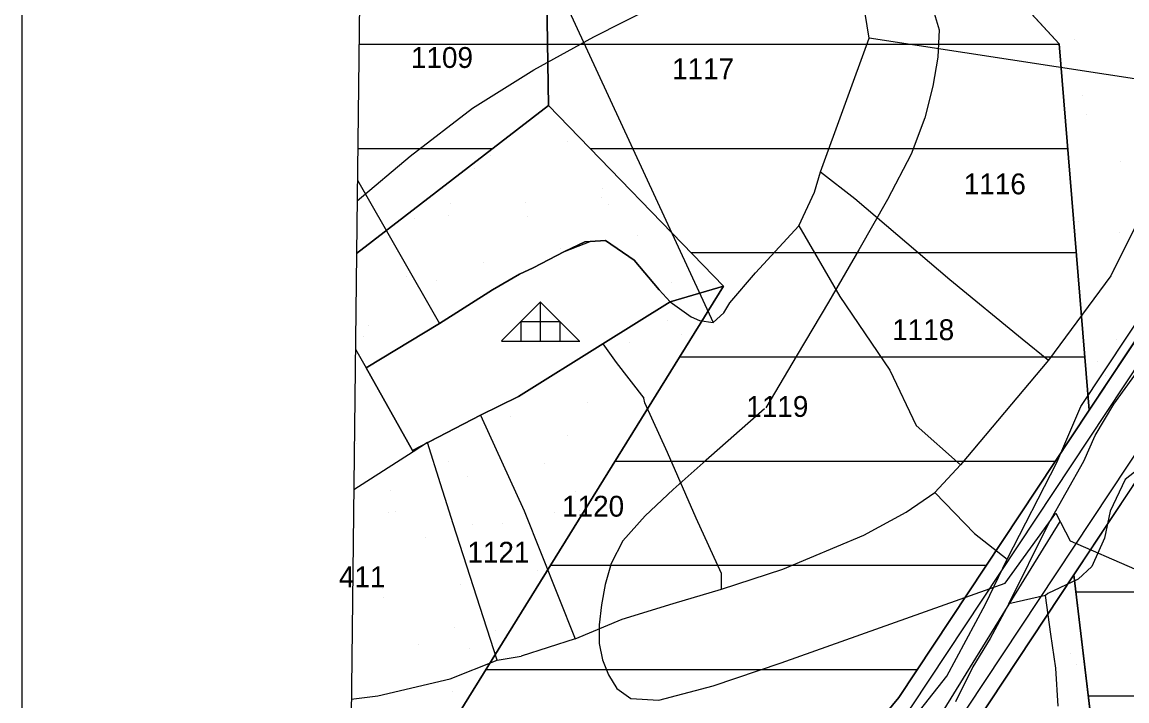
# Model space of a CAD drawing. Extents: x 410727 to 412947, y 4463506 to 4466382.
# Drawn here: x 410732.3 to 410944.2, y 4466165.1 to 4466295.3 of the extents above; entities that cross this region are included whole.
import ezdxf

# ---------------------------------------------------------------- set-up
doc = ezdxf.new("R2010")
doc.units = 0
for name, color, linetype in [('ADAKENARI', 7, 'Continuous'), ('KALDIRIM', 7, 'Continuous'), ('KDS_PARSEL_NO', 7, 'Continuous'), ('KDS_PL', 7, 'Continuous'), ('LJ_ÇERÇEVE', 7, 'Continuous'), ('PL_AYA_ORMAN', 7, 'Continuous'), ('PL_AYA_PARK_DINLENME', 7, 'Continuous'), ('PL_KON_ONE_50', 7, 'Continuous'), ('TR_GELİŞME_KONUT_ÇOKAZ', 7, 'Continuous'), ('TR_ORMAN', 7, 'Continuous'), ('TR_PARKALANI', 7, 'Continuous'), ('Yerlesime_uygunluk_sınırı', 7, 'Continuous')]:
    doc.layers.add(name, color=color, linetype=linetype)

msp = doc.modelspace()

# ---------------------------------------------------------------- linework, layer by layer
at = {"layer": 'ADAKENARI'}
for p, q in [((410931.26, 4466291.1), (410905.8, 4466318.77)), ((410984.87, 4466293.13), (410937.01, 4466220.86)), ((410937.01, 4466220.86), (410931.26, 4466291.1)), ((410934.05, 4466189.23), (410970.35, 4466244.04)), ((410937.01, 4466220.86), (410900.49, 4466165.73)), ((410938.28, 4466153.9), (410934.05, 4466189.23))]:
    msp.add_line(p, q, dxfattribs=at)
for points in [[(410795.11, 4466136.69), (410805.11, 4466144.92), (410866.88, 4466244.62), (410833.32, 4466279.27), (410832.84, 4466307.82), (410865.03, 4466330.16), (410877.28, 4466326.74), (410905.8, 4466318.77), (410931.26, 4466291.1), (410937.01, 4466220.86), (410900.49, 4466165.73), (410879.24, 4466140.03), (410850.95, 4466105.81), (410843.66, 4466098.87), (410832.15, 4466087.93), (410816.2, 4466116.02), (410794.68, 4466100.2)], [(410816.68, 4466331), (410832.84, 4466307.82), (410833.32, 4466279.27), (410796.46, 4466250.92)], [(410796.46, 4466250.92), (410833.32, 4466279.27), (410866.88, 4466244.62), (410856.65, 4466241.61), (410854.49, 4466243.9), (410849.71, 4466249.6), (410844.2, 4466253.37), (410840.27, 4466253.16), (410836.39, 4466251.28), (410830.37, 4466248.16), (410827.75, 4466246.92), (410822.57, 4466243.9), (410812.36, 4466237.47), (410798.29, 4466228.95), (410807.2, 4466213.12), (410820.24, 4466219.87), (410827.53, 4466223.46), (410843.7, 4466233.54), (410856.65, 4466241.61), (410866.88, 4466244.62), (410805.11, 4466144.92)], [(410940.58, 4466134.71), (410895.48, 4466136.13), (410912.56, 4466156.78), (410934.05, 4466189.23), (410938.28, 4466153.9), (410940.58, 4466134.71)]]:
    msp.add_lwpolyline(points, dxfattribs=at)
at = {"layer": 'KALDIRIM'}
msp.add_lwpolyline([(410877.26, 4466132.92), (410902.91, 4466163.94), (410984.73, 4466287.49), (410992.24, 4466282.52), (410910.15, 4466158.57), (410883.93, 4466126.86)], dxfattribs=at)
at = {"layer": 'KDS_PL'}
for p, q in [((410834.19, 4466304.11), (410864.85, 4466237.66)), ((410894.78, 4466292.22), (410893.62, 4466299.29)), ((410885.49, 4466266.55), (410894.78, 4466292.22)), ((410958.96, 4466282.37), (410894.78, 4466292.22)), ((410884.31, 4466262.69), (410885.49, 4466266.55)), ((410885.49, 4466266.55), (410892.04, 4466261.44)), ((410796.63, 4466264.96), (410812.36, 4466237.47)), ((410881.3, 4466256.2), (410884.31, 4466262.69)), ((410892.04, 4466261.44), (410910.29, 4466245.88)), ((410947.29, 4466258.94), (410941.14, 4466246.62)), ((410872.97, 4466247.16), (410881.3, 4466256.2)), ((410881.3, 4466256.2), (410889.16, 4466242.64)), ((410836.39, 4466251.28), (410841.26, 4466253.22)), ((410841.26, 4466253.22), (410844.2, 4466253.37)), ((410844.2, 4466253.37), (410849.71, 4466249.6)), ((410830.37, 4466248.16), (410836.39, 4466251.28)), ((410935.37, 4466221.54), (410954.9, 4466251.01)), ((410849.71, 4466249.6), (410854.49, 4466243.9)), ((410822.57, 4466243.9), (410827.75, 4466246.92)), ((410827.75, 4466246.92), (410830.37, 4466248.16)), ((410868.06, 4466241.46), (410872.97, 4466247.16)), ((410941.14, 4466246.62), (410929.18, 4466230.45)), ((410910.29, 4466245.88), (410924.12, 4466234.54)), ((410812.36, 4466237.47), (410822.57, 4466243.9)), ((410854.49, 4466243.9), (410856.65, 4466241.61)), ((410889.16, 4466242.64), (410898.78, 4466228.51)), ((410843.7, 4466233.54), (410856.65, 4466241.61)), ((410856.65, 4466241.61), (410860.66, 4466238.72)), ((410866.95, 4466239.49), (410868.06, 4466241.46)), ((410860.66, 4466238.72), (410862.23, 4466238.06)), ((410862.23, 4466238.06), (410864.85, 4466237.66)), ((410864.85, 4466237.66), (410866.95, 4466239.49)), ((410798.29, 4466228.95), (410812.36, 4466237.47)), ((410924.12, 4466234.54), (410929.18, 4466230.45)), ((410827.53, 4466223.46), (410843.7, 4466233.54)), ((410843.7, 4466233.54), (410846.3, 4466230)), ((410846.3, 4466230), (410851.58, 4466223.15)), ((410929.18, 4466230.45), (410912.3, 4466210.35)), ((410941.71, 4466221.99), (410948.25, 4466231)), ((410798.29, 4466228.95), (410807.35, 4466212.86)), ((410898.78, 4466228.51), (410903.83, 4466217.9)), ((410820.24, 4466219.87), (410827.53, 4466223.46)), ((410851.79, 4466222.26), (410851.58, 4466223.15)), ((410856.15, 4466212.71), (410851.79, 4466222.26)), ((410930.81, 4466210.8), (410935.37, 4466221.54)), ((410938.16, 4466215.99), (410941.71, 4466221.99)), ((410810.09, 4466214.62), (410820.24, 4466219.87)), ((410820.24, 4466219.87), (410828.62, 4466201.51)), ((410912.3, 4466210.35), (410903.83, 4466217.9)), ((410810.09, 4466214.62), (410807.35, 4466212.86)), ((410812.58, 4466206.72), (410810.09, 4466214.62)), ((410935.98, 4466211.07), (410938.16, 4466215.99)), ((410807.35, 4466212.86), (410795.93, 4466205.55)), ((410861.6, 4466200.15), (410856.15, 4466212.71)), ((410907.37, 4466205.07), (410912.3, 4466210.35)), ((410921.27, 4466192.23), (410930.81, 4466210.8)), ((410929.17, 4466199.06), (410935.98, 4466211.07)), ((410949.7, 4466212.12), (410943.9, 4466207.55)), ((410813.85, 4466202.7), (410812.58, 4466206.72)), ((410943.9, 4466207.55), (410941.06, 4466201.49)), ((410901.92, 4466201.24), (410907.37, 4466205.07)), ((410907.37, 4466205.07), (410915, 4466197.15)), ((410815, 4466199.06), (410813.85, 4466202.7)), ((410828.62, 4466201.51), (410838.43, 4466176.94)), ((410866.5, 4466189.5), (410861.6, 4466200.15)), ((410893.75, 4466196.87), (410901.92, 4466201.24)), ((410941.06, 4466201.49), (410939.95, 4466196.3)), ((410823.44, 4466172.85), (410815, 4466199.06)), ((410921.57, 4466183.69), (410929.17, 4466199.06)), ((410878.22, 4466190.32), (410893.75, 4466196.87)), ((410915, 4466197.15), (410921.27, 4466192.23)), ((410939.95, 4466196.3), (410937.48, 4466190.86)), ((410917.14, 4466183.62), (410921.27, 4466192.23)), ((410866.5, 4466186.5), (410878.22, 4466190.32)), ((410866.5, 4466186.5), (410866.5, 4466189.5)), ((410937.48, 4466190.86), (410934.89, 4466188.39)), ((410934.89, 4466188.39), (410929.09, 4466185.67)), ((410857.23, 4466183.77), (410866.5, 4466186.5)), ((410928.6, 4466185.3), (410921.57, 4466183.69)), ((410929.09, 4466185.67), (410928.6, 4466185.3)), ((410929.64, 4466177.86), (410928.6, 4466185.3)), ((410847.42, 4466180.76), (410857.23, 4466183.77)), ((410909.67, 4466169.8), (410917.14, 4466183.62)), ((410921.57, 4466183.69), (410917.99, 4466177.01)), ((410838.43, 4466176.94), (410847.42, 4466180.76)), ((410838.43, 4466176.94), (410828.08, 4466173.67)), ((410917.99, 4466177.01), (410914.66, 4466171.57)), ((410930.61, 4466171.31), (410929.64, 4466177.86)), ((410814.45, 4466169.3), (410823.44, 4466172.85)), ((410823.44, 4466172.85), (410828.08, 4466173.67)), ((410914.66, 4466171.57), (410911.33, 4466164.9)), ((410931.03, 4466164.06), (410930.61, 4466171.31)), ((410800.55, 4466166.02), (410814.45, 4466169.3)), ((410902.77, 4466161.05), (410909.67, 4466169.8)), ((410795.45, 4466165.4), (410800.55, 4466166.02))]:
    msp.add_line(p, q, dxfattribs=at)
msp.add_lwpolyline([(410796.25, 4466232.55), (410798.29, 4466228.95)], dxfattribs=at)
at = {"layer": 'LJ_ÇERÇEVE'}
msp.add_lwpolyline([(410732.32, 4466381.6), (412946.74, 4466381.6), (412946.74, 4463506.16), (410732.32, 4463506.16)], close=True, dxfattribs=at)
at = {"layer": 'PL_AYA_ORMAN'}
msp.add_lwpolyline([(410856.65, 4466241.61), (410854.49, 4466243.9), (410849.71, 4466249.6), (410844.2, 4466253.37), (410840.27, 4466253.16), (410836.39, 4466251.28), (410830.37, 4466248.16), (410827.75, 4466246.92), (410822.57, 4466243.9), (410812.36, 4466237.47), (410798.29, 4466228.95), (410807.2, 4466213.12), (410820.24, 4466219.87), (410827.53, 4466223.46), (410843.7, 4466233.54), (410856.65, 4466241.61)], dxfattribs=at)
at = {"layer": 'PL_AYA_PARK_DINLENME'}
for points in [[(410966.77, 4466329.24), (410952.62, 4466329.41), (410948.75, 4466326.83), (410945.69, 4466329.49), (410864.92, 4466330.44), (410865.03, 4466330.16), (410905.8, 4466318.77), (410931.26, 4466291.1), (410937.01, 4466220.86), (410984.87, 4466293.13), (410984.62, 4466304.63), (410966.77, 4466329.24)], [(410796.46, 4466250.92), (410795.35, 4466156.58), (410805.11, 4466144.92), (410866.88, 4466244.62), (410833.32, 4466279.27), (410796.46, 4466250.92)], [(410843.7, 4466233.54), (410827.53, 4466223.46), (410820.24, 4466219.87), (410807.2, 4466213.12), (410798.29, 4466228.95), (410812.36, 4466237.47), (410822.57, 4466243.9), (410827.75, 4466246.92), (410830.37, 4466248.16), (410836.39, 4466251.28), (410840.27, 4466253.16), (410844.2, 4466253.37), (410849.71, 4466249.6), (410854.49, 4466243.9), (410856.65, 4466241.61), (410843.7, 4466233.54)], [(410938.28, 4466153.9), (410934.05, 4466189.23), (410912.56, 4466156.78), (410895.48, 4466136.13), (410940.58, 4466134.71), (410938.28, 4466153.9)]]:
    msp.add_lwpolyline(points, dxfattribs=at)
at = {"layer": 'PL_KON_ONE_50'}
for points in [[(410816.68, 4466331), (410797.42, 4466331.23), (410796.46, 4466250.92), (410833.32, 4466279.27), (410866.88, 4466244.62), (410805.11, 4466144.92), (410795.11, 4466136.69), (410794.68, 4466100.2), (410816.2, 4466116.02), (410832.15, 4466087.93), (410843.66, 4466098.87), (410850.95, 4466105.81), (410879.24, 4466140.03), (410900.49, 4466165.73), (410937.01, 4466220.86), (410931.26, 4466291.1), (410905.8, 4466318.77), (410877.28, 4466326.74), (410865.03, 4466330.16), (410861.62, 4466327.79), (410841.62, 4466313.92), (410832.84, 4466307.82), (410821.62, 4466323.91), (410816.68, 4466331)], [(411018.73, 4466159.08), (411019.64, 4466094.39), (411040.6, 4466094.16), (411083.21, 4466088.38), (411127.43, 4466096.15), (411139.34, 4466102.02), (411143.99, 4466106.28), (411135.74, 4466178.25), (411069.2, 4466174.92), (411071.88, 4466196.56), (411061.36, 4466220.11), (411049.97, 4466245.63), (410970.35, 4466244.04), (410934.05, 4466189.23), (410938.28, 4466153.9), (410984.99, 4466158.37), (411018.73, 4466159.08)]]:
    msp.add_lwpolyline(points, dxfattribs=at)
at = {"layer": 'TR_GELİŞME_KONUT_ÇOKAZ'}
for p, q in [((410796.94, 4466291.07), (410833.12, 4466291.07)), ((410833.12, 4466291.07), (410833.12, 4466291.07)), ((410833.12, 4466291.07), (410931.26, 4466291.07)), ((410796.7, 4466271.07), (410822.65, 4466271.07)), ((410841.27, 4466271.07), (410932.9, 4466271.07)), ((410796.47, 4466251.07), (410796.66, 4466251.07)), ((410860.64, 4466251.07), (410934.54, 4466251.07)), ((410858.48, 4466231.07), (410936.17, 4466231.07)), ((410846.09, 4466211.07), (410930.52, 4466211.07)), ((410833.7, 4466191.07), (410917.28, 4466191.07)), ((410934.44, 4466186), (411014.83, 4466186)), ((410821.31, 4466171.07), (410904.03, 4466171.07)), ((410936.83, 4466166), (411137.14, 4466166))]:
    msp.add_line(p, q, dxfattribs=at)
at = {"layer": 'TR_ORMAN'}
for p, q in [((410824.29, 4466234.11), (410831.78, 4466241.61)), ((410839.19, 4466234.15), (410831.69, 4466241.65)), ((410831.79, 4466234.1), (410831.79, 4466241.6)), ((410828.04, 4466234.1), (410828.04, 4466237.85)), ((410828.04, 4466237.85), (410835.54, 4466237.85)), ((410835.54, 4466234.1), (410835.54, 4466237.85)), ((410824.29, 4466234.1), (410839.29, 4466234.1))]:
    msp.add_line(p, q, dxfattribs=at)
at = {"layer": 'TR_PARKALANI'}
for p, q in [((410934.19, 4466291.93), (410934.19, 4466291.93)), ((410934.19, 4466291.93), (410934.19, 4466291.93)), ((410934.19, 4466291.93), (410934.19, 4466291.93)), ((410935.67, 4466281.18), (410935.67, 4466281.18)), ((410935.67, 4466281.18), (410935.67, 4466281.18)), ((410935.67, 4466281.18), (410935.67, 4466281.18)), ((410935.67, 4466281.18), (410935.67, 4466281.18)), ((410935.67, 4466281.18), (410935.67, 4466281.18)), ((410935.67, 4466281.18), (410935.67, 4466281.18)), ((410936.44, 4466277.62), (410936.44, 4466277.62)), ((410936.44, 4466277.62), (410936.44, 4466277.62)), ((410936.44, 4466277.62), (410936.44, 4466277.62)), ((410936.44, 4466277.62), (410936.44, 4466277.62)), ((410936.44, 4466277.62), (410936.44, 4466277.62)), ((410936.44, 4466277.62), (410936.44, 4466277.62)), ((410836.97, 4466272.35), (410836.97, 4466272.35)), ((410836.97, 4466272.35), (410836.97, 4466272.35)), ((410822.2, 4466269.74), (410822.2, 4466269.74)), ((410822.2, 4466269.74), (410822.2, 4466269.74)), ((410943.1, 4466268.64), (410943.1, 4466268.64)), ((410943.1, 4466268.64), (410943.1, 4466268.64)), ((410943.1, 4466268.64), (410943.1, 4466268.64)), ((410943.1, 4466268.64), (410943.1, 4466268.64)), ((410943.1, 4466268.64), (410943.1, 4466268.64)), ((410943.1, 4466268.64), (410943.1, 4466268.64)), ((410819.09, 4466267.26), (410819.09, 4466267.26)), ((410843.63, 4466263.37), (410843.63, 4466263.37)), ((410843.63, 4466263.37), (410843.63, 4466263.37)), ((410843.44, 4466261.58), (410843.44, 4466261.58)), ((410843.44, 4466261.58), (410843.44, 4466261.58)), ((410814.42, 4466260.58), (410814.42, 4466260.58)), ((410828.86, 4466260.76), (410828.86, 4466260.76)), ((410828.86, 4466260.76), (410828.86, 4466260.76)), ((410844.84, 4466260.3), (410844.84, 4466260.3)), ((410807.6, 4466257.62), (410807.6, 4466257.62)), ((410807.6, 4466257.62), (410807.6, 4466257.62)), ((410814.09, 4466258.16), (410814.09, 4466258.16)), ((410814.09, 4466258.16), (410814.09, 4466258.16)), ((410829.2, 4466257.98), (410829.2, 4466257.98)), ((410934.99, 4466257.05), (410934.99, 4466257.05)), ((410934.99, 4466257.05), (410934.99, 4466257.05)), ((410934.99, 4466257.05), (410934.99, 4466257.05)), ((410934.99, 4466257.05), (410934.99, 4466257.05)), ((410934.99, 4466257.05), (410934.99, 4466257.05)), ((410934.99, 4466257.05), (410934.99, 4466257.05)), ((410942.88, 4466254.86), (410942.88, 4466254.86)), ((410942.88, 4466254.86), (410942.88, 4466254.86)), ((410942.88, 4466254.86), (410942.88, 4466254.86)), ((410850.29, 4466254.39), (410850.29, 4466254.39)), ((410850.29, 4466254.39), (410850.29, 4466254.39)), ((410835.52, 4466251.78), (410835.52, 4466251.78)), ((410835.52, 4466251.78), (410835.52, 4466251.78)), ((410820.75, 4466249.18), (410820.75, 4466249.18)), ((410820.75, 4466249.18), (410820.75, 4466249.18)), ((410805.97, 4466246.57), (410805.97, 4466246.57)), ((410805.97, 4466246.57), (410805.97, 4466246.57)), ((410941.65, 4466248.08), (410941.65, 4466248.08)), ((410941.65, 4466248.08), (410941.65, 4466248.08)), ((410941.65, 4466248.08), (410941.65, 4466248.08)), ((410941.65, 4466248.08), (410941.65, 4466248.08)), ((410941.65, 4466248.08), (410941.65, 4466248.08)), ((410941.65, 4466248.08), (410941.65, 4466248.08)), ((410811.82, 4466245.81), (410811.82, 4466245.81)), ((410856.95, 4466245.41), (410856.95, 4466245.41)), ((410856.95, 4466245.41), (410856.95, 4466245.41)), ((410856.14, 4466238), (410856.14, 4466238)), ((410798.71, 4466237.11), (410798.71, 4466237.11)), ((410797.86, 4466234.99), (410797.86, 4466234.99)), ((410797.86, 4466234.99), (410797.86, 4466234.99)), ((410848.84, 4466233.82), (410848.84, 4466233.82)), ((410848.84, 4466233.82), (410848.84, 4466233.82)), ((410858.89, 4466235.39), (410858.89, 4466235.39)), ((410858.89, 4466235.39), (410858.89, 4466235.39)), ((410942.23, 4466234.47), (410942.23, 4466234.47)), ((410942.23, 4466234.47), (410942.23, 4466234.47)), ((410942.23, 4466234.47), (410942.23, 4466234.47)), ((410938.54, 4466230.23), (410938.54, 4466230.23)), ((410938.54, 4466230.23), (410938.54, 4466230.23)), ((410938.54, 4466230.23), (410938.54, 4466230.23)), ((410940.2, 4466227.51), (410940.2, 4466227.51)), ((410940.2, 4466227.51), (410940.2, 4466227.51)), ((410940.2, 4466227.51), (410940.2, 4466227.51)), ((410940.2, 4466227.51), (410940.2, 4466227.51)), ((410940.2, 4466227.51), (410940.2, 4466227.51)), ((410940.2, 4466227.51), (410940.2, 4466227.51)), ((410840.73, 4466222.24), (410840.73, 4466222.24)), ((410840.73, 4466222.24), (410840.73, 4466222.24)), ((410825.96, 4466219.63), (410825.96, 4466219.63)), ((410825.96, 4466219.63), (410825.96, 4466219.63)), ((410837.02, 4466215.98), (410837.02, 4466215.98)), ((410796.41, 4466214.42), (410796.41, 4466214.42)), ((410796.41, 4466214.42), (410796.41, 4466214.42)), ((410847.39, 4466213.26), (410847.39, 4466213.26)), ((410847.39, 4466213.26), (410847.39, 4466213.26)), ((410814.16, 4466210.91), (410814.16, 4466210.91)), ((410832.62, 4466210.65), (410832.62, 4466210.65)), ((410832.62, 4466210.65), (410832.62, 4466210.65)), ((410817.84, 4466208.05), (410817.84, 4466208.05)), ((410817.84, 4466208.05), (410817.84, 4466208.05)), ((410803.07, 4466205.44), (410803.07, 4466205.44)), ((410803.07, 4466205.44), (410803.07, 4466205.44)), ((410838.51, 4466205.23), (410838.51, 4466205.23)), ((410838.51, 4466205.23), (410838.51, 4466205.23)), ((410802.67, 4466201.27), (410802.67, 4466201.27)), ((410802.67, 4466201.27), (410802.67, 4466201.27)), ((410804, 4466201.49), (410804, 4466201.49)), ((410834.42, 4466201.21), (410834.42, 4466201.21)), ((410839.28, 4466201.67), (410839.28, 4466201.67)), ((410839.28, 4466201.67), (410839.28, 4466201.67)), ((410818.78, 4466198.89), (410818.78, 4466198.89)), ((410824.51, 4466199.07), (410824.51, 4466199.07)), ((410824.51, 4466199.07), (410824.51, 4466199.07)), ((410809.73, 4466196.46), (410809.73, 4466196.46)), ((410809.73, 4466196.46), (410809.73, 4466196.46)), ((410831.17, 4466190.09), (410831.17, 4466190.09)), ((410831.17, 4466190.09), (410831.17, 4466190.09)), ((410816.39, 4466187.48), (410816.39, 4466187.48)), ((410816.39, 4466187.48), (410816.39, 4466187.48)), ((410801.4, 4466186.72), (410801.4, 4466186.72)), ((410801.62, 4466184.88), (410801.62, 4466184.88)), ((410801.62, 4466184.88), (410801.62, 4466184.88)), ((410829.62, 4466184.71), (410829.62, 4466184.71)), ((410815.3, 4466179.19), (410815.3, 4466179.19)), ((410823.05, 4466178.5), (410823.05, 4466178.5)), ((410823.05, 4466178.5), (410823.05, 4466178.5)), ((410808.28, 4466175.9), (410808.28, 4466175.9)), ((410808.28, 4466175.9), (410808.28, 4466175.9)), ((410818.13, 4466175.07), (410818.13, 4466175.07)), ((410818.13, 4466175.07), (410818.13, 4466175.07)), ((410933.5, 4466174.2), (410933.5, 4466174.2)), ((410934.59, 4466172.07), (410934.59, 4466172.07)), ((410934.59, 4466172.07), (410934.59, 4466172.07)), ((410814.94, 4466166.92), (410814.94, 4466166.92)), ((410814.94, 4466166.92), (410814.94, 4466166.92))]:
    msp.add_line(p, q, dxfattribs=at)
at = {"layer": 'Yerlesime_uygunluk_sınırı'}
for points in [[(410806.76, 4466269.56), (410818.73, 4466278.77), (410830.45, 4466286.15), (410842.01, 4466292.49), (410853.38, 4466298.25), (410864.39, 4466303.28), (410874.44, 4466306.67), (410882.7, 4466307.05), (410889.92, 4466305.79), (410896.59, 4466303.85), (410902.55, 4466301.45), (410906.88, 4466298.29), (410908.25, 4466293.79), (410907.98, 4466288.57), (410907, 4466282.98), (410905.45, 4466276.95), (410902.84, 4466269.96), (410898.34, 4466261.23), (410892.85, 4466251.58), (410887, 4466241.58), (410881.01, 4466231.46), (410874.98, 4466221.3)], [(410796.58, 4466260.99), (410806.76, 4466269.56)], [(410874.75, 4466221.09), (410868.82, 4466215.91), (410862.93, 4466210.73), (410857.18, 4466205.59), (410851.84, 4466200.54), (410847.58, 4466195.75), (410845.33, 4466191.44), (410844.18, 4466187.4), (410843.48, 4466183.47), (410843.04, 4466179.67), (410843.01, 4466176.09), (410843.67, 4466172.92), (410844.8, 4466170.04), (410846.42, 4466167.46), (410849.08, 4466165.51), (410854.46, 4466165.22), (410864.85, 4466167.97), (410877.95, 4466172.37), (410920.91, 4466187.62), (410930.63, 4466201.1), (410933.38, 4466195.79), (410945.72, 4466190.37)], [(410794.02, 4466044.48), (410814.72, 4466061.06), (410872.79, 4466121.33), (410901.75, 4466151.38), (410931.46, 4466199.49)]]:
    msp.add_lwpolyline(points, dxfattribs=at)

# ---------------------------------------------------------------- texts
at = {"layer": 'KDS_PARSEL_NO'}
for s, p in [('1109', (410806.91, 4466286.5)), ('1117', (410857, 4466284.34)), ('1116', (410912.95, 4466262.25)), ('1118', (410899.21, 4466234.27)), ('1119', (410871.24, 4466219.55)), ('1120', (410835.9, 4466200.41)), ('1121', (410817.74, 4466191.58)), ('411', (410793.09, 4466186.86))]:
    msp.add_text(s, height=4, dxfattribs=at).set_placement(p)

doc.saveas('drawing.dxf')
